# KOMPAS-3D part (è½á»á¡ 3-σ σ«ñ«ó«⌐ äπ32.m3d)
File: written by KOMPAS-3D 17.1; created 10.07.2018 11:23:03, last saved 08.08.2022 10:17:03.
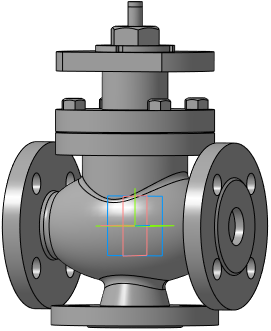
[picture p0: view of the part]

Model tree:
1. Операция без истории:3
